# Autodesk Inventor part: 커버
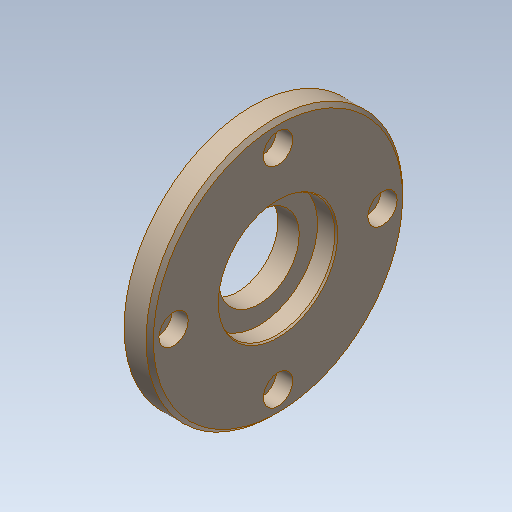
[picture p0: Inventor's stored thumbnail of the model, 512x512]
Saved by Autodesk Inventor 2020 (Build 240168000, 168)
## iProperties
Created: 2024-02
Part Number: 커버
Material: 알루미늄 6061
Document SubType Name: Modeling
Designer: mdu-01
Density: 1 g/cm^3
Appearance: 기본값(1)
Author: mdu-01
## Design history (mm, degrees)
sketch "스케치1"
  geometry: L1 (0, 0)-(12, 0); L2 (0, 20.5)-(0, 22.5); L3 (1, 23.5)-(5, 23.5); L4 (5, 23.5)-(5, 35); L5 (5, 35)-(11, 35); L6 (12, 34)-(12, 16.289); L7 (11.5, 16)-(6.8, 16); L8 (6.8, 16)-(6.8, 11); L9 (6.8, 11)-(1, 11); L10 (1, 11)-(1, 20.5); L11 (1, 20.5)-(0, 20.5); L12 (11.5, 16)-(12, 16.289); L13 (0, 22.5)-(1, 23.5); L14 (11, 35)-(12, 34); 3 further points
  constraints: 28 end point, 8 parallel, 8 point on line, 2 perpendicular, 1 horizontal
  dimensions: "d0" = 12 distance of L1.start L1.end; "d1" = 70 diameter of L5 L1; "d2" = 5 distance between parallel lines of L4 L2; "d3" = 47 diameter of L3 L1; "d4" = 41 diameter of L11 L1; "d5" = 22 diameter of L9 L1; "d6" = 32 diameter of L7 L1; "d7" = 1 distance between parallel lines of L2 L10; "d8" = 5.2 distance between parallel lines of L6 L8; "d10" = 0.5 distance of L7.start point (12, 16); "d11" = 30 deg angle of L7 L12; "d12" = 1 distance of L2.end point (0, 23.5); "d13" = 1 distance of L3.start point (0, 23.5) (= d12); "d14" = 1 distance of L5.end point (12, 35); "d15" = 1 distance of L6.start point (12, 35) (= d14)
revolve "회전1" sketch "스케치1" stored, may be unused: angle "d16" = 90 deg
sketch "스케치2" dims "d17" = 57
  geometry: 3 further points
  constraints: 2 vertical alignment, 1 coincident, 2 other
hole "구멍1" sketch "스케치2" at (0, 28.5) diameter "d18" = 4.5; stored, may be unused: countersink angle "d22" = 90 deg, drill point angle "d24" = 118 deg; dims "d19" = 6, "d20" = 8, "d21" = 4.4, "d23" = 8
node "솔리드1"
pattern_circular "원형 패턴1" dims angle "d26" = 360 deg
